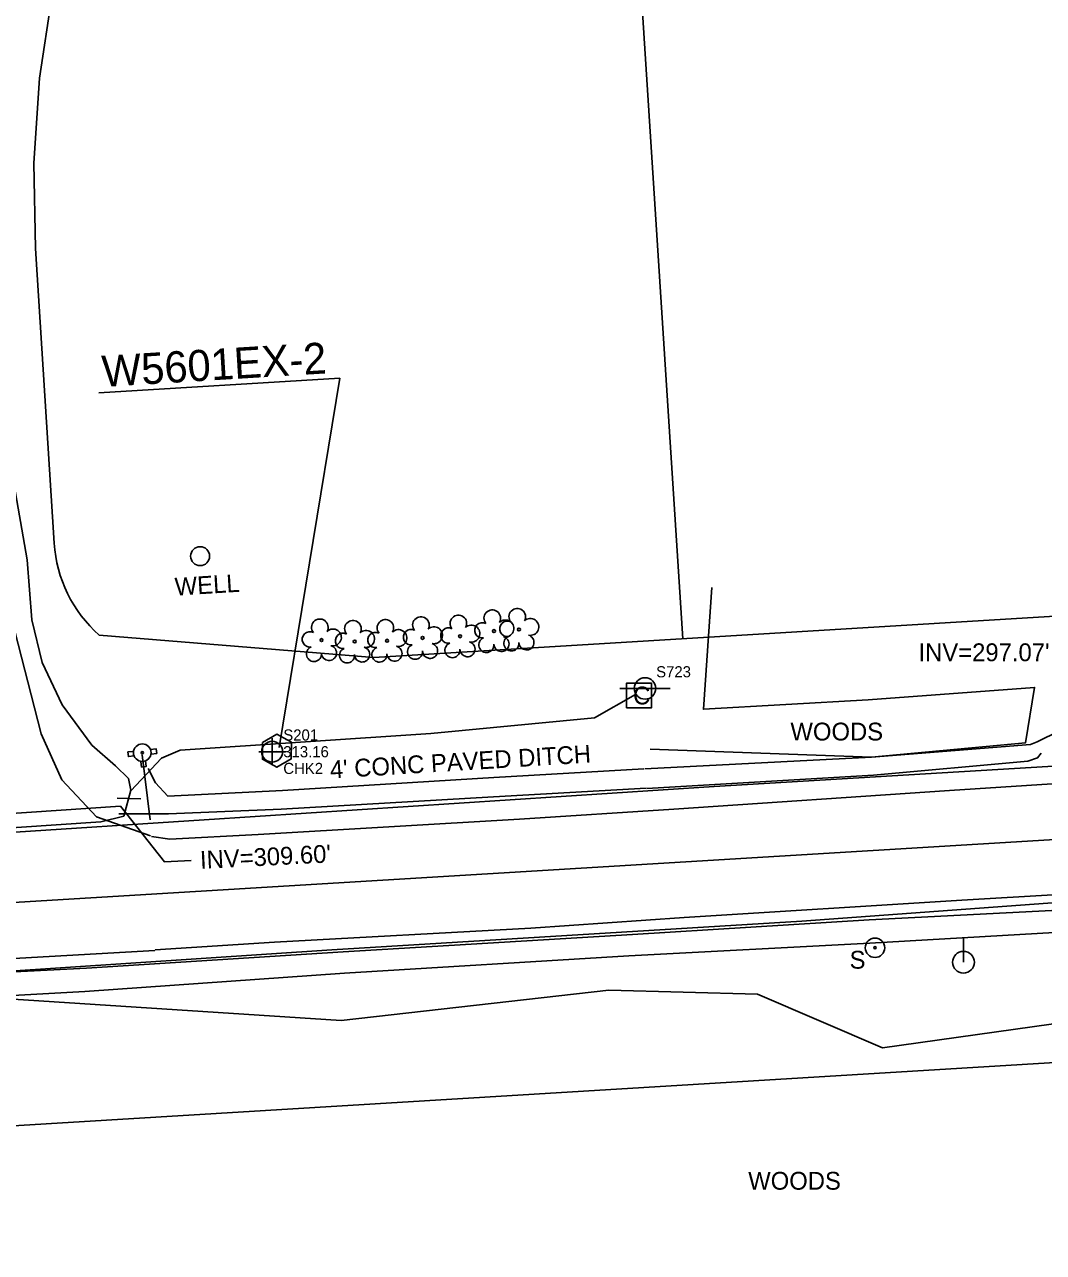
# Model space of a CAD drawing. Extents: x 2110969 to 2113691, y 670003 to 672285.
# Drawn here: x 2112747.7 to 2112976.4, y 670433.2 to 670708.7 of the extents above; entities that cross this region are included whole.
import ezdxf

# ---------------------------------------------------------------- set-up
doc = ezdxf.new("R2010")
doc.units = 0
for name, color, linetype in [('Default', 7, 'Continuous'), ('Default Symbol CELL', 7, 'Continuous'), ('Default Symbol Cogo Comment', 7, 'Continuous'), ('Default Symbol Cogo Elevation', 7, 'Continuous'), ('Default Symbol Cogo Number', 7, 'Continuous'), ('Exist Horizontal Alignment', 7, 'Continuous'), ('Exist Horizontal Baseline Alignment Station Label', 7, 'Continuous'), ('Exist Other Culture Sign Text', 7, 'Continuous'), ('Exist Other Culture Well CELL', 7, 'Continuous'), ('Exist Other Culture Well Text', 7, 'Continuous'), ('Exist Property Line', 7, 'Continuous'), ('Exist Right of Way Line', 7, 'Continuous'), ('Exist Roads EOP', 7, 'Continuous'), ('Exist Roads EOP Other', 7, 'Continuous'), ('Exist Structure Minor Paved Ditch or Gutter', 7, 'Continuous'), ('Exist Structure Minor Paved Ditch or Gutter Text', 7, 'Continuous'), ('Exist Structure Minor Pipes RCP 18 Inch', 7, 'Continuous'), ('Exist Structure Minor Pipes RCP 18 Inch Invert', 7, 'Continuous'), ('Exist Structure Minor Pipes RCP 18 Inch Leader', 7, 'Continuous'), ('Exist Utilities Power Pole CELL', 7, 'Continuous'), ('Exist Utilities Telephone Pole CELL', 7, 'Continuous'), ('Exist Utilities Telephone Pole Cogo Number', 7, 'Continuous'), ('Exist Utilities Telephone UG FO SUE LOS B', 7, 'Continuous'), ('Exist Utilities TV Pedestal CELL', 7, 'Continuous'), ('Exist Utilities TV UG Cable SUE LOS B', 7, 'Continuous'), ('Exist Utilities Water Fire Hydrant CELL', 7, 'Continuous'), ('Exist Utilities Water UG Line SUE LOS B', 7, 'Continuous'), ('Exist Vegetation Tree CELL', 7, 'Continuous'), ('Exist Vegetation Woods Line', 7, 'Continuous'), ('Exist Vegetation Woods Line Text', 7, 'Continuous')]:
    doc.layers.add(name, color=color, linetype=linetype)

msp = doc.modelspace()

# ---------------------------------------------------------------- linework, layer by layer
at = {"layer": 'Default'}
for radius in [2.18, 0.24]:
    msp.add_circle((2112938.61, 670501.58), radius, dxfattribs=at)
at = {"layer": 'Default Symbol CELL'}
msp.add_lwpolyline([(2112803.29, 670548.57), (2112803.29, 670542.57), (2112803.29, 670545.57), (2112806.29, 670545.57), (2112800.29, 670545.57)], dxfattribs=at)
msp.add_circle((2112803.29, 670545.57), 2.34, dxfattribs=at)
at = {"layer": 'Exist Horizontal Alignment'}
msp.add_line((2111597.13, 670442.15), (2113362.13, 670549.12), dxfattribs=at)
at = {"layer": 'Exist Horizontal Baseline Alignment Station Label'}
for p, q in [((2112818.51, 670629.39), (2112764.36, 670626.11)), ((2112804.34, 670545.79), (2112804.34, 670545.79))]:
    msp.add_line(p, q, dxfattribs=at)
msp.add_lwpolyline([(2112818.51, 670629.39), (2112804.88, 670546.5)], dxfattribs=at)
msp.add_lwpolyline([(2112801.11, 670547.66), (2112804.36, 670549.48), (2112807.61, 670547.69), (2112807.56, 670543.96), (2112804.31, 670542.08), (2112801.11, 670543.89)], close=True, dxfattribs=at)
at = {"layer": 'Exist Other Culture Well CELL'}
msp.add_circle((2112787.12, 670589.45), 2.13, dxfattribs=at)
at = {"layer": 'Exist Property Line'}
msp.add_line((2112895.43, 670570.93), (2112869.82, 670970.41), dxfattribs=at)
at = {"layer": 'Exist Right of Way Line'}
for p, q in [((2112751.06, 670696.74), (2112753.92, 670715.68)), ((2112749.81, 670677.62), (2112751.06, 670696.74)), ((2112750.19, 670658.46), (2112749.81, 670677.62)), ((2112750.19, 670658.47), (2112754.37, 670592.36)), ((2112826.13, 670566.73), (2113691.32, 670619.17)), ((2112764.46, 670571.75), (2112826.13, 670566.73)), ((2112275.95, 670433.2), (2113479.86, 670506.17))]:
    msp.add_line(p, q, dxfattribs=at)
msp.add_arc((2112784.31, 670594.25), 30, 183.6161, 228.5763, dxfattribs=at)
at = {"layer": 'Exist Roads EOP'}
for points in [[(2112738.73, 670614.95), (2112744.81, 670575.56), (2112751.41, 670549.57), (2112756.08, 670539.25), (2112763.89, 670530.93), (2112775.96, 670526.66)], [(2113361.19, 670561.38), (2113300, 670557.8), (2113237.06, 670554.42), (2113180.42, 670550.57), (2113120.04, 670546.64), (2113071.3, 670543.72), (2113048.98, 670542.29), (2113046.06, 670543.23), (2113044.6, 670543.86), (2113023.33, 670542.83), (2113021.27, 670541.64), (2113013.84, 670541.76), (2113009.46, 670540.39), (2112955.35, 670536.89), (2112893.42, 670532.66), (2112858.8, 670530.45), (2112800.17, 670526.96), (2112780.32, 670525.95), (2112776.24, 670526.52)], [(2113362.39, 670537.44), (2113297.78, 670533.58), (2113239.25, 670529.55), (2113180.88, 670526), (2113122.41, 670522.43), (2113072.9, 670519.62), (2113025.73, 670516.23), (2112958.1, 670512.29), (2112895.8, 670508.35), (2112861.36, 670506), (2112803.82, 670502.84), (2112777.04, 670501.11)], [(2112239.79, 670466.76), (2112249.04, 670469.51), (2112290.21, 670472.2), (2112340.18, 670475.23), (2112395.57, 670478.46), (2112425.73, 670480.47), (2112476.62, 670483.47), (2112528.49, 670486.45), (2112578.55, 670489.44), (2112632.17, 670492.66), (2112690.33, 670496.03), (2112733.41, 670498.51), (2112776.92, 670500.99)]]:
    msp.add_lwpolyline(points, dxfattribs=at)
at = {"layer": 'Exist Roads EOP Other'}
msp.add_line((2112768.49, 670535.17), (2112773.84, 670534.97), dxfattribs=at)
at = {"layer": 'Exist Structure Minor Paved Ditch or Gutter'}
for points in [[(2112886.95, 670541.73), (2112937.79, 670544.35), (2112973.54, 670547.17), (2112975.01, 670547.8), (2112979.99, 670550.22), (2112980.72, 670545.78)], [(2112887.4, 670537.33), (2112938.29, 670540.31), (2112972.87, 670543.46), (2112975.09, 670544.21), (2112975.88, 670545.27)], [(2112775.46, 670541.83), (2112777.13, 670538.56), (2112779.89, 670535.58), (2112805.6, 670536.89), (2112853.08, 670539.8), (2112886.73, 670541.69)], [(2112887.26, 670537.35), (2112852.99, 670535.45), (2112805.32, 670532.68), (2112780.05, 670531.64), (2112776.33, 670531.63), (2112768.86, 670531.62)], [(2112988.55, 670510.48), (2112937.28, 670507.84), (2112884.19, 670504.54), (2112819.22, 670500.65), (2112761.65, 670497.03), (2112707.07, 670494.25), (2112651.72, 670490.01)], [(2112987.94, 670505.51), (2112937.44, 670502.6), (2112883.37, 670499.77), (2112819.5, 670495.9), (2112761.24, 670491.77), (2112707.32, 670488.73), (2112652.43, 670485.21)]]:
    msp.add_lwpolyline(points, dxfattribs=at)
at = {"layer": 'Exist Structure Minor Pipes RCP 18 Inch'}
msp.add_line((2112769.27, 670533.32), (2112695.88, 670528.5), dxfattribs=at)
at = {"layer": 'Exist Structure Minor Pipes RCP 18 Inch Leader'}
msp.add_lwpolyline([(2112769.27, 670533.32), (2112779.1, 670520.86), (2112785.09, 670521.16)], dxfattribs=at)
at = {"layer": 'Exist Utilities Power Pole CELL'}
for q in [(2112958.45, 670503.94), (2112958.45, 670498.32)]:
    msp.add_line((2112958.45, 670498.32), q, dxfattribs=at)
msp.add_circle((2112958.45, 670498.32), 2.45, dxfattribs=at)
at = {"layer": 'Exist Utilities Telephone Pole CELL'}
for p, q in [((2112881.3, 670559.76), (2112892.64, 670559.76)), ((2112881.3, 670559.76), (2112892.64, 670559.76)), ((2112881.3, 670559.76), (2112892.64, 670559.76)), ((2112886.98, 670559.76), (2112886.98, 670559.76)), ((2112886.98, 670559.76), (2112886.98, 670559.76)), ((2112886.98, 670559.76), (2112886.98, 670559.76))]:
    msp.add_line(p, q, dxfattribs=at)
msp.add_circle((2112886.98, 670559.76), 2.41, dxfattribs=at)
msp.add_circle((2112886.98, 670559.76), 2.41, dxfattribs=at)
msp.add_circle((2112886.98, 670559.76), 2.41, dxfattribs=at)
at = {"layer": 'Exist Utilities Telephone UG FO SUE LOS B'}
msp.add_lwpolyline([(2112667.68, 670491.25), (2112816.71, 670501.11), (2112922.17, 670507.55), (2112995.79, 670512.91), (2113269.89, 670527.3)], dxfattribs=at)
msp.add_lwpolyline([(2112667.68, 670491.25), (2112816.71, 670501.11), (2112922.17, 670507.55), (2112995.79, 670512.91), (2113269.89, 670527.3)], dxfattribs=at)
at = {"layer": 'Exist Utilities TV Pedestal CELL'}
msp.add_line((2112885.62, 670558.18), (2112885.62, 670558.18), dxfattribs=at)
msp.add_line((2112885.62, 670558.18), (2112885.62, 670558.18), dxfattribs=at)
msp.add_lwpolyline([(2112882.85, 670555.4), (2112888.4, 670555.4), (2112888.4, 670560.95), (2112882.85, 670560.95), (2112882.85, 670555.4)], dxfattribs=at)
msp.add_lwpolyline([(2112882.85, 670555.4), (2112888.4, 670555.4), (2112888.4, 670560.95), (2112882.85, 670560.95), (2112882.85, 670555.4)], dxfattribs=at)
at = {"layer": 'Exist Utilities TV UG Cable SUE LOS B'}
for points in [[(2112663.97, 670544.66), (2112667.07, 670541.61), (2112678.84, 670538.5), (2112687.51, 670534.39), (2112692.19, 670530.83), (2112694.25, 670526.49), (2112695.98, 670525.24), (2112726.93, 670527.3), (2112764.82, 670529.82), (2112769.96, 670531.12), (2112771.59, 670536.91), (2112771.01, 670539.59), (2112768.09, 670542.37), (2112762.83, 670547.06), (2112756.12, 670556.06), (2112751.68, 670565.58), (2112749.36, 670575.14), (2112748.31, 670588.62), (2112745.07, 670607.1), (2112743.37, 670627.4)], [(2112663.97, 670544.66), (2112667.07, 670541.61), (2112678.84, 670538.5), (2112687.51, 670534.39), (2112692.19, 670530.83), (2112694.25, 670526.49), (2112695.98, 670525.24), (2112726.93, 670527.3), (2112764.82, 670529.82), (2112769.96, 670531.12), (2112771.59, 670536.91), (2112771.01, 670539.59), (2112768.09, 670542.37), (2112762.83, 670547.06), (2112756.12, 670556.06), (2112751.68, 670565.58), (2112749.36, 670575.14), (2112748.31, 670588.62), (2112745.07, 670607.1), (2112743.37, 670627.4)], [(2112771.6, 670536.79), (2112778.47, 670544.13), (2112782.61, 670545.89), (2112838.94, 670549.65), (2112875.61, 670553.16), (2112884.82, 670558.39)], [(2112771.6, 670536.79), (2112778.47, 670544.13), (2112782.61, 670545.89), (2112838.94, 670549.65), (2112875.61, 670553.16), (2112884.82, 670558.39)]]:
    msp.add_lwpolyline(points, dxfattribs=at)
at = {"layer": 'Exist Utilities Water Fire Hydrant CELL'}
msp.add_line((2112774.14, 670545.35), (2112774.14, 670545.35), dxfattribs=at)
msp.add_line((2112774.14, 670545.35), (2112774.14, 670545.35), dxfattribs=at)
for points in [[(2112772.29, 670544.63), (2112771.01, 670544.49), (2112770.9, 670545.51), (2112772.21, 670545.65)], [(2112772.29, 670544.63), (2112771.01, 670544.49), (2112770.9, 670545.51), (2112772.21, 670545.65)], [(2112776.1, 670545.05), (2112777.38, 670545.19), (2112777.26, 670546.2), (2112775.96, 670546.06)], [(2112776.1, 670545.05), (2112777.38, 670545.19), (2112777.26, 670546.2), (2112775.96, 670546.06)], [(2112773.84, 670543.39), (2112773.98, 670542.11), (2112775, 670542.22), (2112774.86, 670543.5)], [(2112773.84, 670543.39), (2112773.98, 670542.11), (2112775, 670542.22), (2112774.86, 670543.5)]]:
    msp.add_lwpolyline(points, dxfattribs=at)
for radius in [1.98, 1.98, 0.243, 0.243]:
    msp.add_circle((2112774.14, 670545.35), radius, dxfattribs=at)
at = {"layer": 'Exist Utilities Water UG Line SUE LOS B'}
msp.add_line((2112774.1, 670544.84), (2112775.9, 670530.28), dxfattribs=at)
msp.add_line((2112774.1, 670544.84), (2112775.9, 670530.28), dxfattribs=at)
msp.add_lwpolyline([(2112063.12, 670452.82), (2112061.08, 670490.25), (2112149, 670492.87), (2112291.17, 670500.39), (2112417.24, 670508.2), (2112519.46, 670514.32), (2112696.23, 670524.3), (2112788.03, 670530.3), (2112902.5, 670537.78), (2113013.6, 670544.43), (2113214.88, 670557.36), (2113313.23, 670563.26)], dxfattribs=at)
msp.add_lwpolyline([(2112063.12, 670452.82), (2112061.08, 670490.25), (2112149, 670492.87), (2112291.17, 670500.39), (2112417.24, 670508.2), (2112519.46, 670514.32), (2112696.23, 670524.3), (2112788.03, 670530.3), (2112902.5, 670537.78), (2113013.6, 670544.43), (2113214.88, 670557.36), (2113313.23, 670563.26)], dxfattribs=at)
at = {"layer": 'Exist Vegetation Tree CELL'}
for p, q in [((2112858.69, 670572.99), (2112858.69, 670572.99)), ((2112814.37, 670570.62), (2112814.37, 670570.62)), ((2112821.81, 670570.29), (2112821.81, 670570.29)), ((2112829.08, 670570.48), (2112829.08, 670570.48)), ((2112837.06, 670571.11), (2112837.06, 670571.11)), ((2112845.46, 670571.48), (2112845.46, 670571.48)), ((2112853.08, 670572.64), (2112853.08, 670572.64))]:
    msp.add_line(p, q, dxfattribs=at)
for centre in [(2112853.08, 670572.64), (2112858.69, 670572.99), (2112814.37, 670570.62), (2112821.81, 670570.29), (2112829.08, 670570.48), (2112837.06, 670571.11), (2112845.46, 670571.48)]:
    msp.add_circle(centre, 0.326, dxfattribs=at)
for centre, radius, start, end in [((2112836.68, 670573.99), 1.86, 330.1651, 219.7134), ((2112845.08, 670574.36), 1.86, 330.1651, 219.7134), ((2112852.69, 670575.52), 1.86, 330.1651, 219.7134), ((2112858.3, 670575.86), 1.86, 330.1651, 219.7134), ((2112813.99, 670573.49), 1.86, 330.1651, 219.7134), ((2112816.92, 670571.21), 1.9, 257.1011, 134.1999), ((2112821.42, 670573.16), 1.86, 330.1651, 219.7134), ((2112828.7, 670573.35), 1.86, 330.1651, 219.7134), ((2112831.63, 670571.07), 1.9, 257.1011, 134.1999), ((2112834.46, 670571.27), 1.73, 62.6636, 279.3457), ((2112839.61, 670571.7), 1.9, 257.1011, 134.1999), ((2112842.86, 670571.64), 1.73, 62.6636, 279.3457), ((2112848.01, 670572.07), 1.9, 257.1011, 134.1999), ((2112850.47, 670572.8), 1.73, 62.6636, 279.3457), ((2112855.63, 670573.23), 1.9, 257.1011, 134.1999), ((2112856.08, 670573.14), 1.73, 62.6636, 279.3457), ((2112861.24, 670573.58), 1.9, 257.1011, 134.1999), ((2112811.76, 670570.77), 1.73, 62.6636, 279.3457), ((2112819.2, 670570.44), 1.73, 62.6636, 279.3457), ((2112824.36, 670570.88), 1.9, 257.1011, 134.1999), ((2112826.47, 670570.63), 1.73, 62.6636, 279.3457), ((2112847.14, 670568.58), 1.7, 181.2822, 74.56), ((2112851.37, 670569.52), 1.69, 111.5671, 6.231), ((2112854.75, 670569.74), 1.7, 181.2822, 74.56), ((2112856.98, 670569.87), 1.69, 111.5671, 6.231), ((2112860.36, 670570.09), 1.7, 181.2822, 74.56), ((2112812.67, 670567.5), 1.69, 111.5671, 6.231), ((2112816.04, 670567.72), 1.7, 181.2822, 74.56), ((2112820.1, 670567.17), 1.69, 111.5671, 6.231), ((2112823.48, 670567.39), 1.7, 181.2822, 74.56), ((2112827.38, 670567.36), 1.69, 111.5671, 6.231), ((2112830.75, 670567.58), 1.7, 181.2822, 74.56), ((2112835.36, 670567.99), 1.69, 111.5671, 6.231), ((2112838.73, 670568.21), 1.7, 181.2822, 74.56), ((2112843.76, 670568.36), 1.69, 111.5671, 6.231)]:
    msp.add_arc(centre, radius, start, end, dxfattribs=at)
at = {"layer": 'Exist Vegetation Woods Line'}
msp.add_line((2112818.81, 670485.27), (2112878.84, 670492.06), dxfattribs=at)
for points in [[(2112901.99, 670582.45), (2112900.09, 670555.1), (2112937.08, 670557.24), (2112974.41, 670560), (2112972.36, 670547.54), (2112937.79, 670544.35), (2112888.15, 670546.16)], [(2112544.87, 670453.63), (2112557.66, 670475.73), (2112641.37, 670483.3), (2112714.03, 670492.02), (2112818.81, 670485.27)], [(2112878.84, 670492.06), (2112912.2, 670491.14), (2112940.26, 670479.15), (2113012.26, 670489.19)]]:
    msp.add_lwpolyline(points, dxfattribs=at)

# ---------------------------------------------------------------- texts
at = {"layer": 'Default Symbol Cogo Comment'}
msp.add_text('CHK2', height=2.5, dxfattribs=at).set_placement((2112805.79, 670540.57))
at = {"layer": 'Default Symbol Cogo Elevation'}
msp.add_text('313.16', height=2.5, dxfattribs=at).set_placement((2112805.79, 670544.32))
at = {"layer": 'Default Symbol Cogo Number'}
msp.add_text('S201', height=2.5, dxfattribs=at).set_placement((2112805.79, 670548.07))
at = {"layer": 'Exist Horizontal Baseline Alignment Station Label'}
msp.add_text('W5601EX-2', height=7, rotation=3.4682, dxfattribs=at).set_placement((2112765.28, 670627.42))
at = {"layer": 'Exist Other Culture Sign Text'}
msp.add_text('S', height=4, dxfattribs=at).set_placement((2112932.9, 670496.88))
at = {"layer": 'Exist Other Culture Well Text'}
msp.add_text('WELL', height=4, rotation=3.4682, dxfattribs=at).set_placement((2112781.54, 670580.58))
at = {"layer": 'Exist Structure Minor Paved Ditch or Gutter Text'}
msp.add_text("4' CONC PAVED DITCH", height=4, rotation=3.5122, dxfattribs=at).set_placement((2112816.37, 670539.55))
at = {"layer": 'Exist Structure Minor Pipes RCP 18 Inch Invert'}
msp.add_text("INV=297.07'", height=4, dxfattribs=at).set_placement((2112948.36, 670565.88))
msp.add_text("INV=309.60'", height=4, rotation=2.8644, dxfattribs=at).set_placement((2112787.19, 670519.26))
at = {"layer": 'Exist Utilities Telephone Pole Cogo Number'}
msp.add_text('S723', height=2.5, dxfattribs=at).set_placement((2112889.48, 670562.26))
at = {"layer": 'Exist Utilities TV Pedestal CELL'}
msp.add_text('C', height=4, dxfattribs=at).set_placement((2112884.31, 670556.18))
msp.add_text('C', height=4, dxfattribs=at).set_placement((2112884.31, 670556.18))
at = {"layer": 'Exist Vegetation Woods Line Text'}
for p in [(2112919.62, 670548.09), (2112910.14, 670447.28)]:
    msp.add_text('WOODS', height=4, dxfattribs=at).set_placement(p)

doc.saveas('drawing.dxf')
